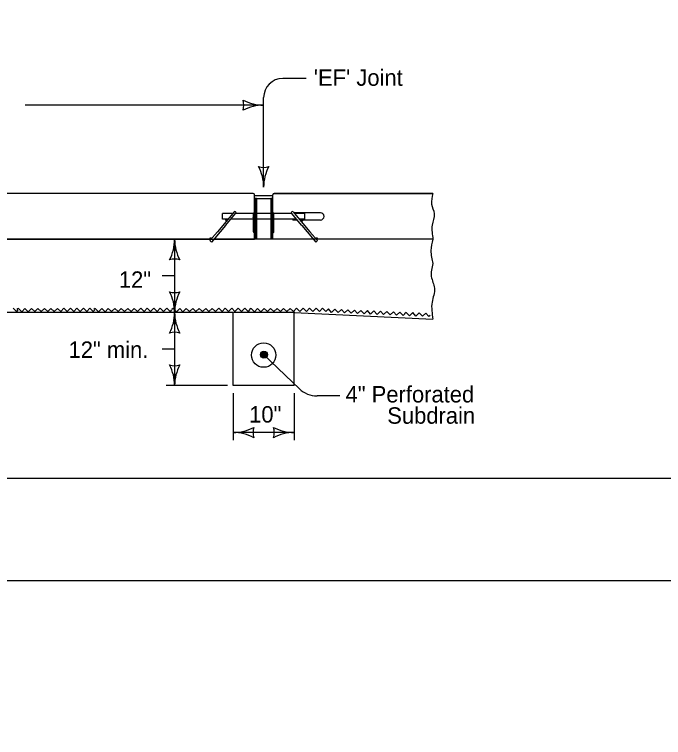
# Model space of a CAD drawing. Extents: x 10130 to 81668, y 5440 to 21644.
# Drawn here: x 15102 to 15735, y 7771 to 8476 of the extents above; entities that cross this region are included whole.
import ezdxf

# ---------------------------------------------------------------- set-up
doc = ezdxf.new("R2010")
doc.units = 0
for name, color, linetype in [('dsnNonPlotable', 7, 'Continuous'), ('dsnShtPlotShapeBatchPrint', 7, 'Continuous'), ('dsnStdBlock', 7, 'Continuous'), ('dsnStdBlockModified', 7, 'Continuous'), ('dsnStdBlockNotModified', 7, 'Continuous'), ('dsnStdBorder', 7, 'Continuous'), ('SheetBorder', 7, 'Continuous')]:
    doc.layers.add(name, color=color, linetype=linetype)

msp = doc.modelspace()

# ---------------------------------------------------------------- linework, layer by layer
at = {"layer": 'dsnNonPlotable'}
msp.add_line((15345.17, 8387.38), (15112.91, 8387.38), dxfattribs=at)
for centre, radius, start, end in [((15309.32, 8387.38), 16.51, 342.26665, 17.73335), ((15345.17, 8430.13), 42.75, 241.92751, 270), ((15309.32, 8387.38), 16.51, 342.26665, 17.73335), ((15345.17, 8430.13), 42.75, 241.92751, 270), ((15345.17, 8344.63), 42.75, 90, 118.07249), ((15345.17, 8344.63), 42.75, 90, 118.07249)]:
    msp.add_arc(centre, radius, start, end, dxfattribs=at)
at = {"layer": 'dsnShtPlotShapeBatchPrint'}
msp.add_lwpolyline([(13698.67, 5439.62), (17042.67, 5439.62), (17042.67, 8023.62), (13698.67, 8023.62)], close=True, dxfattribs=at)
at = {"layer": 'dsnStdBlock'}
for p, q in [((15335.01, 8301.31), (14227.94, 8301.31)), ((15336.26, 8270.31), (15336.26, 8300.06)), ((15354.08, 8298.9), (15336.26, 8298.9)), ((15354.08, 8270.31), (15354.08, 8300.06)), ((15510.17, 8301.31), (15355.32, 8301.31)), ((15338.04, 8296.5), (15336.26, 8296.5)), ((15336.43, 8296.5), (15336.43, 8270.31)), ((15336.61, 8296.5), (15336.61, 8270.31)), ((15336.79, 8296.5), (15336.79, 8270.31)), ((15336.97, 8296.5), (15336.97, 8270.31)), ((15337.15, 8296.5), (15337.15, 8270.31)), ((15337.33, 8296.5), (15337.33, 8270.31)), ((15337.5, 8296.5), (15337.5, 8270.31)), ((15337.68, 8296.5), (15337.68, 8270.31)), ((15337.86, 8296.5), (15337.86, 8270.31)), ((15338.04, 8296.5), (15338.04, 8281.71)), ((15338.04, 8296.5), (15352.29, 8296.5)), ((15338.04, 8281.71), (15338.04, 8296.5)), ((15352.29, 8296.5), (15352.29, 8281.71)), ((15352.29, 8296.5), (15352.29, 8281.71)), ((15354.08, 8296.5), (15352.29, 8296.5)), ((15352.47, 8296.5), (15352.47, 8270.31)), ((15352.65, 8296.5), (15352.65, 8270.31)), ((15352.83, 8296.5), (15352.83, 8270.31)), ((15353.01, 8296.5), (15353.01, 8270.31)), ((15353.19, 8296.5), (15353.19, 8270.31)), ((15353.36, 8296.5), (15353.36, 8270.31)), ((15353.54, 8296.5), (15353.54, 8270.31)), ((15353.72, 8296.5), (15353.72, 8270.31)), ((15353.9, 8296.5), (15353.9, 8270.31)), ((15305.07, 8276.36), (15305.07, 8281.71)), ((15314.87, 8281.71), (15305.07, 8281.71)), ((15316.35, 8283.47), (15305.3, 8270.31)), ((15308.1, 8270.31), (15317.98, 8282.09)), ((15314.87, 8281.71), (15314.87, 8281.71)), ((15335.19, 8281.71), (15317.66, 8281.71)), ((15335.19, 8263.89), (15335.19, 8281.71)), ((15335.19, 8281), (15335.19, 8281)), ((15338.04, 8281.71), (15338.04, 8276.36)), ((15352.29, 8281.71), (15338.04, 8281.71)), ((15352.29, 8281.71), (15352.29, 8276.36)), ((15354.61, 8282.24), (15354.61, 8282.24)), ((15355.15, 8263.89), (15355.15, 8281.71)), ((15372.67, 8281.71), (15355.15, 8281.71)), ((15382.24, 8270.31), (15372.35, 8282.09)), ((15373.99, 8283.47), (15385.03, 8270.31)), ((15400.41, 8282.6), (15374.71, 8282.6)), ((15375.46, 8281.71), (15375.46, 8281.71)), ((15385.26, 8281.71), (15375.46, 8281.71)), ((15385.26, 8276.36), (15385.26, 8281.71)), ((15305.3, 8270.31), (15300.05, 8264.04)), ((15308.1, 8270.31), (15302.83, 8264.04)), ((15310.39, 8276.36), (15305.07, 8276.36)), ((15335.19, 8276.36), (15313.18, 8276.36)), ((15336.26, 8264.04), (15336.26, 8270.31)), ((15336.43, 8270.31), (15336.43, 8264.04)), ((15336.61, 8270.31), (15336.61, 8264.04)), ((15336.79, 8270.31), (15336.79, 8264.04)), ((15336.97, 8270.31), (15336.97, 8264.04)), ((15337.15, 8270.31), (15337.15, 8264.04)), ((15337.33, 8270.31), (15337.33, 8264.04)), ((15337.5, 8270.31), (15337.5, 8264.04)), ((15337.68, 8270.31), (15337.68, 8264.04)), ((15337.86, 8270.31), (15337.86, 8264.04)), ((15352.29, 8276.36), (15338.04, 8276.36)), ((15338.04, 8276.36), (15338.04, 8270.31)), ((15338.04, 8270.31), (15338.04, 8264.04)), ((15352.29, 8276.36), (15352.29, 8270.31)), ((15352.29, 8270.31), (15352.29, 8264.04)), ((15352.47, 8270.31), (15352.47, 8264.04)), ((15352.65, 8270.31), (15352.65, 8264.04)), ((15352.83, 8270.31), (15352.83, 8264.04)), ((15353.01, 8270.31), (15353.01, 8264.04)), ((15353.19, 8270.31), (15353.19, 8264.04)), ((15353.36, 8270.31), (15353.36, 8264.04)), ((15353.54, 8270.31), (15353.54, 8264.04)), ((15353.72, 8270.31), (15353.72, 8264.04)), ((15353.9, 8270.31), (15353.9, 8264.04)), ((15354.08, 8264.04), (15354.08, 8270.31)), ((15377.16, 8276.36), (15355.15, 8276.36)), ((15373.68, 8276.36), (15373.68, 8275.47)), ((15377.9, 8275.47), (15373.68, 8275.47)), ((15385.26, 8276.36), (15379.94, 8276.36)), ((15400.41, 8275.47), (15380.7, 8275.47)), ((15382.24, 8270.31), (15387.5, 8264.04)), ((15385.03, 8270.31), (15390.29, 8264.04)), ((15300.05, 8264.04), (15292.8, 8255.4)), ((15302.83, 8264.04), (15294.44, 8254.03)), ((15336.26, 8256.76), (15336.26, 8264.04)), ((15336.43, 8264.04), (15336.43, 8256.76)), ((15336.61, 8264.04), (15336.61, 8256.76)), ((15336.79, 8264.04), (15336.79, 8256.76)), ((15336.97, 8264.04), (15336.97, 8256.76)), ((15337.15, 8264.04), (15337.15, 8256.76)), ((15337.33, 8264.04), (15337.33, 8256.76)), ((15337.5, 8264.04), (15337.5, 8256.76)), ((15337.68, 8264.04), (15337.68, 8256.76)), ((15337.86, 8264.04), (15337.86, 8256.76)), ((15338.04, 8264.04), (15338.04, 8256.76)), ((15352.29, 8264.04), (15352.29, 8256.76)), ((15352.47, 8264.04), (15352.47, 8256.76)), ((15352.65, 8264.04), (15352.65, 8256.76)), ((15352.83, 8264.04), (15352.83, 8256.76)), ((15353.01, 8264.04), (15353.01, 8256.76)), ((15353.19, 8264.04), (15353.19, 8256.76)), ((15353.36, 8264.04), (15353.36, 8256.76)), ((15353.54, 8264.04), (15353.54, 8256.76)), ((15353.72, 8264.04), (15353.72, 8256.76)), ((15353.9, 8264.04), (15353.9, 8256.76)), ((15354.08, 8256.76), (15354.08, 8264.04)), ((15355.15, 8263.89), (15355.15, 8263.89)), ((15387.5, 8264.04), (15395.89, 8254.03)), ((15390.29, 8264.04), (15397.53, 8255.4)), ((15293.94, 8256.76), (14227.94, 8256.76)), ((15294.44, 8254.03), (15292.8, 8255.4)), ((15338.04, 8256.76), (15296.73, 8256.76)), ((15352.29, 8256.76), (15338.04, 8256.76)), ((15393.6, 8256.76), (15352.29, 8256.76)), ((15395.89, 8254.03), (15397.53, 8255.4)), ((15510.17, 8256.76), (15396.39, 8256.76)), ((15315.47, 8185.48), (14227.94, 8185.48)), ((15315.47, 8114.2), (15315.47, 8185.48)), ((15375.49, 8185.48), (15316.09, 8185.48)), ((15374.87, 8114.2), (15374.87, 8185.48)), ((15374.87, 8185.48), (15510.17, 8178.93)), ((15374.87, 8114.2), (15315.47, 8114.2))]:
    msp.add_line(p, q, dxfattribs=at)
for points in [[(15352.29, 8296.36), (15352.15, 8296.5)], [(15352.29, 8276.07), (15352, 8276.36)], [(15105.78, 8187.97), (15104.21, 8186.38), (15101.02, 8189.54)], [(15180.67, 8187.97), (15179.1, 8186.38), (15175.91, 8189.54), (15172.76, 8186.36), (15169.58, 8189.52), (15166.42, 8186.34), (15163.25, 8189.5), (15160.09, 8186.32), (15156.91, 8189.48), (15153.75, 8186.3), (15150.57, 8189.47), (15147.41, 8186.29), (15144.23, 8189.45), (15141.08, 8186.27), (15137.9, 8189.43), (15134.74, 8186.26), (15131.57, 8189.42), (15128.41, 8186.24), (15125.23, 8189.4), (15122.07, 8186.23), (15118.89, 8189.38), (15115.74, 8186.21), (15112.56, 8189.37), (15109.4, 8186.19), (15106.23, 8189.35), (15104.8, 8188.22)], [(15255.52, 8187.97), (15253.94, 8186.38), (15250.76, 8189.54), (15247.6, 8186.36), (15244.42, 8189.52), (15241.26, 8186.34), (15238.09, 8189.5), (15234.93, 8186.32), (15231.75, 8189.48), (15228.6, 8186.3), (15225.41, 8189.47), (15222.25, 8186.29), (15219.08, 8189.45), (15215.92, 8186.27), (15212.74, 8189.43), (15209.58, 8186.26), (15206.41, 8189.42), (15203.25, 8186.24), (15200.08, 8189.4), (15196.92, 8186.23), (15193.73, 8189.38), (15190.58, 8186.21), (15187.41, 8189.37), (15184.24, 8186.19), (15181.07, 8189.35), (15179.64, 8188.22)], [(15331.49, 8187.97), (15329.91, 8186.38), (15326.73, 8189.54), (15323.57, 8186.36), (15320.39, 8189.52), (15317.23, 8186.34), (15314.06, 8189.5), (15310.9, 8186.32), (15307.72, 8189.48), (15304.57, 8186.3), (15301.38, 8189.47), (15298.22, 8186.29), (15295.05, 8189.45), (15291.89, 8186.27), (15288.71, 8189.43), (15285.55, 8186.26), (15282.38, 8189.42), (15279.22, 8186.24), (15276.05, 8189.4), (15272.89, 8186.23), (15269.7, 8189.38), (15266.55, 8186.21), (15263.37, 8189.37), (15260.21, 8186.19), (15257.04, 8189.35), (15255.61, 8188.22)], [(15407.36, 8187.97), (15405.78, 8186.38), (15402.6, 8189.54), (15399.44, 8186.36), (15396.26, 8189.52), (15393.1, 8186.34), (15389.93, 8189.5), (15386.77, 8186.32), (15383.59, 8189.48), (15380.43, 8186.3), (15377.25, 8189.47), (15374.09, 8186.29), (15370.92, 8189.45), (15367.76, 8186.27), (15364.58, 8189.43), (15361.42, 8186.26), (15358.25, 8189.42), (15355.09, 8186.24), (15351.92, 8189.4), (15348.75, 8186.23), (15345.57, 8189.38), (15342.42, 8186.21), (15339.24, 8189.37), (15336.08, 8186.19), (15332.91, 8189.35), (15331.48, 8188.22)], [(15482.6, 8184.04), (15480.95, 8182.53), (15477.93, 8185.82), (15474.62, 8182.79), (15471.59, 8186.11), (15468.3, 8183.07), (15465.26, 8186.37), (15461.96, 8183.35), (15458.93, 8186.64), (15455.63, 8183.62), (15452.6, 8186.92), (15449.3, 8183.89), (15446.28, 8187.2), (15442.97, 8184.17), (15439.94, 8187.47), (15436.65, 8184.44), (15433.61, 8187.74), (15430.31, 8184.71), (15427.29, 8188.02), (15423.98, 8184.98), (15420.95, 8188.29), (15417.65, 8185.27), (15414.62, 8188.56), (15411.32, 8185.54), (15408.29, 8188.83), (15406.65, 8187.32)], [(15507.27, 8182.47), (15506.11, 8181.41), (15503.09, 8184.71), (15499.78, 8181.68), (15496.75, 8184.99), (15493.45, 8181.96), (15490.42, 8185.26), (15487.12, 8182.23), (15484.09, 8185.52), (15482.45, 8184.02)]]:
    msp.add_lwpolyline(points, dxfattribs=at)
for centre, radius in [((15308.86, 8275.65), 0.713), ((15382.22, 8274.76), 0.713), ((15293.6, 8257.48), 0.713), ((15396.73, 8257.48), 0.713), ((15345.17, 8143.9), 11.88)]:
    msp.add_circle(centre, radius, dxfattribs=at)
for centre, radius, start, end in [((15335.01, 8300.07), 1.25, 0, 90), ((15355.32, 8300.07), 1.25, 90, 180), ((15317.16, 8282.78), 1.07, 320.00367, 139.99636), ((15373.17, 8282.78), 1.07, 40.00364, 219.99633), ((15335.72, 8281.71), 0.535, 0, 180), ((15354.61, 8281.71), 0.535, 0, 180), ((15400.41, 8279.04), 3.56, 270, 90), ((15335.72, 8263.89), 0.535, 180, 0), ((15354.61, 8263.89), 0.535, 180, 0)]:
    msp.add_arc(centre, radius, start, end, dxfattribs=at)
for points in [[(15510.17, 8301.31), (15508.81, 8291.02), (15511.38, 8281.64), (15509.41, 8270.46), (15510.17, 8256.76)], [(15335.19, 8281.35), (15335.09, 8281.35), (15335, 8281.36), (15334.93, 8281.35), (15334.86, 8281.36), (15334.81, 8281.34), (15334.75, 8281.35)], [(15335.19, 8281), (15335.09, 8280.99), (15335, 8281), (15334.93, 8280.99), (15334.86, 8281.01), (15334.81, 8280.99), (15334.75, 8280.99)], [(15335.19, 8280.64), (15335.09, 8280.63), (15335, 8280.65), (15334.93, 8280.63), (15334.86, 8280.65), (15334.81, 8280.63), (15334.75, 8280.64)], [(15335.19, 8280.28), (15335.09, 8280.28), (15335, 8280.29), (15334.93, 8280.28), (15334.86, 8280.29), (15334.81, 8280.27), (15334.75, 8280.28)], [(15335.19, 8279.93), (15335.09, 8279.92), (15335, 8279.93), (15334.93, 8279.92), (15334.86, 8279.94), (15334.81, 8279.92), (15334.75, 8279.93)], [(15335.19, 8279.57), (15335.09, 8279.56), (15335, 8279.58), (15334.93, 8279.56), (15334.86, 8279.58), (15334.81, 8279.56), (15334.75, 8279.57)], [(15335.19, 8279.22), (15335.09, 8279.21), (15335, 8279.22), (15334.93, 8279.21), (15334.86, 8279.22), (15334.81, 8279.2), (15334.75, 8279.21)], [(15335.19, 8278.86), (15335.09, 8278.85), (15335, 8278.86), (15334.93, 8278.85), (15334.86, 8278.87), (15334.81, 8278.85), (15334.75, 8278.86)], [(15335.19, 8278.5), (15335.09, 8278.5), (15335, 8278.51), (15334.93, 8278.5), (15334.86, 8278.51), (15334.81, 8278.49), (15334.75, 8278.5)], [(15335.19, 8278.15), (15335.09, 8278.14), (15335, 8278.15), (15334.93, 8278.14), (15334.86, 8278.15), (15334.81, 8278.13), (15334.75, 8278.14)], [(15335.19, 8277.79), (15335.09, 8277.78), (15335, 8277.79), (15334.93, 8277.78), (15334.86, 8277.8), (15334.81, 8277.78), (15334.75, 8277.79)], [(15335.19, 8277.43), (15335.09, 8277.43), (15335, 8277.44), (15334.93, 8277.43), (15334.86, 8277.44), (15334.81, 8277.42), (15334.75, 8277.43)], [(15335.19, 8277.08), (15335.09, 8277.07), (15335, 8277.08), (15334.93, 8277.07), (15334.86, 8277.09), (15334.81, 8277.07), (15334.75, 8277.07)], [(15335.19, 8276.72), (15335.09, 8276.71), (15335, 8276.73), (15334.93, 8276.71), (15334.86, 8276.73), (15334.81, 8276.71), (15334.75, 8276.72)], [(15510.17, 8256.76), (15508.2, 8245.82), (15510.17, 8233)], [(15510.17, 8233), (15508.52, 8220.49), (15511.64, 8209.1), (15509.25, 8195.5), (15510.17, 8178.85)]]:
    msp.add_spline(points, degree=3, dxfattribs=at)
at = {"layer": 'dsnStdBlockModified'}
for p, q in [((15335.01, 8301.31), (14784.02, 8301.31)), ((15336.26, 8300.06), (15336.25, 8300.07)), ((15336.26, 8256.76), (15336.26, 8300.06)), ((14784.02, 8256.76), (15223.11, 8256.76)), ((15223.11, 8256.76), (15336.26, 8256.76))]:
    msp.add_line(p, q, dxfattribs=at)
msp.add_lwpolyline([(15336.25, 8300.07), (15335.92, 8301.06), (15335.01, 8301.31)], dxfattribs=at)
at = {"layer": 'dsnStdBlockNotModified'}
for p, q in [((15386.52, 8413.37), (15363.73, 8413.37)), ((15345.17, 8339.84), (15345.17, 8394.81)), ((15345.17, 8307.45), (15345.17, 8339.84)), ((15258.43, 8256.76), (15258.43, 8185.48)), ((15258.43, 8221.12), (15246.31, 8221.12)), ((15258.43, 8185.48), (15258.43, 8114.2)), ((15258.43, 8149.84), (15246.31, 8149.84)), ((15345.12, 8144.59), (15379.94, 8111.16)), ((15309.89, 8114.2), (15250.31, 8114.2)), ((15315.47, 8106.77), (15315.47, 8061.05)), ((15374.87, 8106.77), (15374.87, 8061.05)), ((15419.33, 8104.2), (15397.25, 8104.2)), ((15374.87, 8068.47), (15315.47, 8068.47))]:
    msp.add_line(p, q, dxfattribs=at)
msp.add_lwpolyline([(15345.75, 8141.12), (15344.57, 8141.65), (15342.76, 8142.21), (15342.4, 8144.06), (15342.66, 8145.68), (15343.82, 8147.17), (15345.55, 8147.02), (15347.37, 8146.76), (15348.25, 8145.31), (15348.41, 8143.78), (15347.33, 8141.77), (15346, 8141.61), (15344.18, 8142.07), (15342.69, 8143.23), (15342.74, 8144.96), (15343.9, 8146.35), (15345.53, 8146.51), (15347.35, 8146.16), (15347.63, 8145.13), (15348, 8143.89), (15347.15, 8142.39), (15345.82, 8142.42), (15344.3, 8142.67), (15343.2, 8143.52), (15343.76, 8145.03), (15344.91, 8145.92), (15346.44, 8145.97), (15346.82, 8145.15), (15347.3, 8144.22), (15346.55, 8143.02), (15345.42, 8142.74), (15344.42, 8143.28), (15344.35, 8144.4), (15344.88, 8145.2), (15345.91, 8145.48), (15346.41, 8145.06), (15346.7, 8144.44), (15346.16, 8143.54), (15345.44, 8143.36), (15344.74, 8143.78), (15344.86, 8144.39), (15345.38, 8144.78), (15346.09, 8144.76), (15346.08, 8144.25), (15345.46, 8143.96)], dxfattribs=at)
msp.add_circle((15345.48, 8144.3), 3.47, dxfattribs=at)
for centre, radius, start, end in [((15363.73, 8394.81), 18.56, 90, 180), ((15345.17, 8343.3), 16.51, 252.26665, 287.73335), ((15302.42, 8307.46), 42.75, 0, 28.07249), ((15387.91, 8307.46), 42.75, 151.92751, 180), ((15215.68, 8256.76), 42.75, 331.92751, 0), ((15301.17, 8256.76), 42.75, 180, 208.07249), ((15258.43, 8220.92), 16.51, 72.26665, 107.73335), ((15258.43, 8221.33), 16.51, 252.26665, 287.73335), ((15215.68, 8185.48), 42.75, 0, 28.07249), ((15301.17, 8185.48), 42.75, 151.92751, 180), ((15215.68, 8185.48), 42.75, 331.92751, 0), ((15301.17, 8185.48), 42.75, 180, 208.07249), ((15258.43, 8149.64), 16.51, 72.26665, 107.73335), ((15258.43, 8150.05), 16.51, 252.26665, 287.73335), ((15215.68, 8114.2), 42.75, 0, 28.07249), ((15301.17, 8114.2), 42.75, 151.92751, 180), ((15397.25, 8129.2), 25, 226.17392, 270), ((15315.47, 8111.22), 42.75, 270, 298.07249), ((15351.31, 8068.48), 16.51, 162.26665, 197.73335), ((15339.02, 8068.48), 16.51, 342.26665, 17.73335), ((15374.87, 8111.22), 42.75, 241.92751, 270), ((15315.47, 8025.73), 42.75, 61.92751, 90), ((15374.87, 8025.73), 42.75, 90, 118.07249)]:
    msp.add_arc(centre, radius, start, end, dxfattribs=at)
at = {"layer": 'dsnStdBorder'}
for p, q in [((15354.08, 8281.75), (15354.07, 8300.07)), ((15355.32, 8301.32), (15510.17, 8301.32)), ((15355.14, 8263.89), (15355.14, 8281.71)), ((15354.08, 8256.77), (15354.08, 8263.85)), ((15393.6, 8256.77), (15354.08, 8256.77)), ((15510.17, 8256.77), (15393.6, 8256.77))]:
    msp.add_line(p, q, dxfattribs=at)
for centre, radius, start, end in [((15355.32, 8300.07), 1.25, 90, 180), ((15354.61, 8281.71), 0.535, 0, 176.27485), ((15354.61, 8263.89), 0.535, 184.7481, 0)]:
    msp.add_arc(centre, radius, start, end, dxfattribs=at)
msp.add_spline([(15510.17, 8301.32), (15508.81, 8291.02), (15511.38, 8281.65), (15509.41, 8270.46), (15510.17, 8256.77)], degree=3, dxfattribs=at)
at = {"layer": 'SheetBorder'}
msp.add_lwpolyline([(13732.52, 9944.02), (16867.53, 9944.02), (16867.53, 7924.02), (13732.52, 7924.02)], close=True, dxfattribs=at)

# ---------------------------------------------------------------- texts
at = {"layer": 'dsnStdBlockNotModified'}
for s, p in [("'EF' Joint", (15394.03, 8406.24)), ('12"', (15204.05, 8209.46)), ('12" min.', (15155.04, 8141.21)), ('4" Perforated', (15424.99, 8097.76)), ('10"', (15331.01, 8078.18)), ('   Subdrain', (15447.76, 8077.05))]:
    msp.add_text(s, height=16, dxfattribs=at).set_placement(p)

doc.saveas('drawing.dxf')
